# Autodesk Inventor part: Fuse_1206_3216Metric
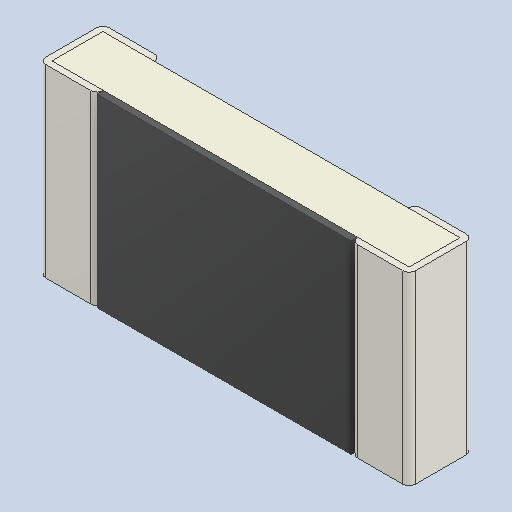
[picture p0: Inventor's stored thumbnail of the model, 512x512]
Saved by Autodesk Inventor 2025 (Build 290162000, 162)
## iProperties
Created: 2026-09
Part Number: Fuse_1206_3216Metric
Material: Generic
Document SubType Name: Modeling
Designer: Leonardo
Density: 1 g/cm^3
Appearance: Default
Author: Leonardo
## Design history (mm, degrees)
feature "Base1"
body "Solid1"
